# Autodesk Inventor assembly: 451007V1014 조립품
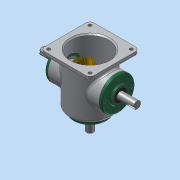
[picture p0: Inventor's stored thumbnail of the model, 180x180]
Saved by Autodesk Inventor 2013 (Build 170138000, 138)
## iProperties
Created: 2015-10
Part Number: 451007V1014 조립품
Document SubType Name: Assembly
Designer: dgall
Author: dgall
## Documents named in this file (14)
- C:\Users\dgall\Desktop\451007V1014\451007V1014 조립품.iam
- C:\Users\dgall\Desktop\451007V1014\본체.ipt
- C:\Users\dgall\Desktop\451007V1014\베어링 6203.ipt
- C:\Users\dgall\Desktop\451007V1014\오일실.ipt
- C:\Users\dgall\Desktop\451007V1014\커버.ipt
- C:\Users\dgall\Desktop\451007V1014\M4.ipt
- C:\Users\dgall\Desktop\451007V1014\서브 베벨기어.ipt
- C:\Users\dgall\Desktop\451007V1014\서브 축.ipt
- 서브 축.ipt
- C:\Users\dgall\Desktop\451007V1014\키 4x4.ipt
- C:\Users\dgall\Desktop\451007V1014\메인 베벨기어.ipt
- C:\Users\dgall\Desktop\451007V1014\메인 축.ipt
- 메인 축.ipt
- C:\Users\dgall\Desktop\451007V1014\키 5x5.ipt
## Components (12 placed, 1 different names)
1. M4:3
2. M4:4
3. M4:5
4. M4:6
5. M4:2
6. M4:7
7. M4:8
8. M4:9
9. M4:1
10. M4:10
11. M4:11
12. M4:12
